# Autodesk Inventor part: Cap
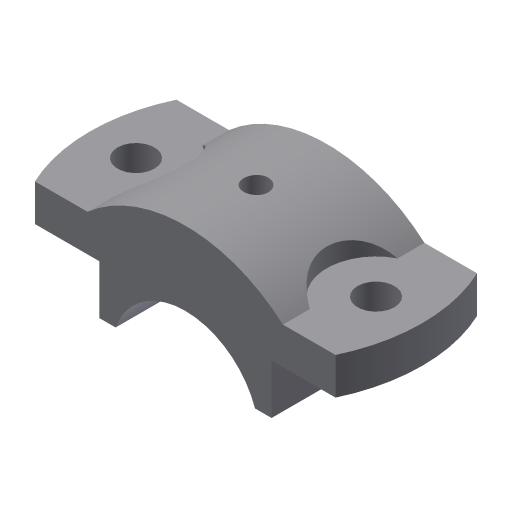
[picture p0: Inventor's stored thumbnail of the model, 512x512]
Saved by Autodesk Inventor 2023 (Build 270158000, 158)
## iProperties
Created: 2009-04
Part Number: Cap
Document SubType Name: Modeling
Designer: Sham
Density: 1 g/cm^3
Material: Generic
Appearance: Default
Mass: 94.0132 g
Surface Area: 184.419 cm^2
Volume: 94.0132 cm^3
Author: Sham
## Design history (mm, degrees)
sketch "Sketch1"
  geometry: L1 (-48.857, 23)-(48.857, 23); L2 (48.857, -23)-(-48.857, -23); A1 r 54 centre (0, 0) between (-48.857, 23) and (-48.857, -23); A2 r 54 centre (0, 0) between (48.857, -23) and (48.857, 23); 1 further point
  constraints: 4 end point, 4 point on circle, 2 centre point, 2 coincident, 1 horizontal, 1 parallel, 1 other
  dimensions: "d3" = 54 radius of A1; "d4" = 54 radius of A2; "d5" = 46 distance between parallel lines of L2 L1; "d6" = 23 distance from line of point (0, 0) L1
extrude "Extrusion1" new body sketch "Sketch1" distance "d7" = 12; taper "d8" = 0 deg
sketch "Sketch3"
  geometry: L1 (20.906, 0)-(20.906, -16); L2 (76.906, -0.137)-(76.906, -16.137); L3 (20.906, -16)-(26.23, -16); L4 (71.532, -16.137)-(76.906, -16.137); L5 (76.906, -0.137)-(76.857, 12); L6 (97.714, 0)-(0, 0) reference; L7 (76.857, 12)-(80.606, 12); L8 (17.108, 12)-(20.906, 12); L9 (20.906, 12)-(20.906, 0); L10 (0, 12)-(97.714, 12) reference; A1 r 24 centre (48.857, -24) between (71.532, -16.137) and (26.23, -16); A2 r 48 centre (48.857, -24) between (80.606, 12) and (17.108, 12); 3 further points
  constraints: 16 end point, 4 point on circle, 3 parallel, 3 perpendicular, 2 centre point, 2 coincident, 2 vertical alignment, 1 collinear, 1 midpoint, 1 vertical, 2 other
  dimensions: "d17" = 48 diameter of A1; "d18" = 16 distance of L1.start L1.end; "d19" = 56 distance between parallel lines of L2 L1; "d21" = 8 vertical distance of A1.centre L1.end; "d22" = 48 radius of A2; "d23" = 0 distance from line of L6 L1.start; "d38" = 31.74902 distance of L7.end point (48.857, 12); "d39" = 28 distance from line of point (48.857, 12) L5
extrude "Extrusion2" join sketch "Sketch3" stored distance "d24" = 12; taper "d25" = 0 deg
sketch "Sketch4"
  geometry: 2 further points
  dimensions: "d26" = 78 distance of point (39, 0) point (-39, 0)
hole "Hole1" sketch "Sketch4" at (-39, 0), (39, 0) diameter "d28" = 12; stored, may be unused: countersink angle "d32" = 90 deg, drill point angle "d34" = 118 deg; dims "d29" = 6, "d30" = 4, "d31" = 2, "d33" = 8
sketch "Sketch5"
  geometry: L1 (-31.749, -23)-(-31.749, 23) reference; L2 (-31.749, 14.263)-(-31.749, -14.263); C1 r 6 at (-39, 0) reference; A1 r 16 centre (-39, 0) between (-31.749, -14.263) and (-31.749, 14.263)
  constraints: 2 end point, 2 point on circle, 1 centre point, 1 coincident, 1 collinear, 1 point on line
  dimensions: "d35" = 16 radius of A1
extrude "Extrusion3" cut sketch "Sketch5" distance "d36" = 12; taper "d37" = 0 deg
mirror "Mirror2"
workplane "Work Plane4"
sketch "Sketch6"
  geometry: L1 (-31.749, 0)-(31.749, 0) reference; 1 further point
  dimensions: "d40" = 23 distance from line of L1 point (0, 23)
hole "Hole2" sketch "Sketch6" at (0, 23) diameter "d41" = 6; stored, may be unused: countersink angle "d45" = 90 deg, drill point angle "d47" = 118 deg; dims "d42" = 6, "d43" = 8, "d44" = 16, "d46" = 8
body "Solid1"
